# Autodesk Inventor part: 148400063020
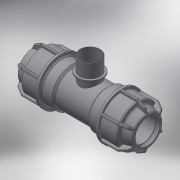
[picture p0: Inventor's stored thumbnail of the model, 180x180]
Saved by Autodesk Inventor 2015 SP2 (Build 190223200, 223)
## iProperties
Created: 2017-08
Part Number: 148400063020
Material: Generic
Description: PLASSON L.14 TEE MALE ADAPTOR (SILVER) 63-2"-63
Document SubType Name: Modeling
Designer: KIM
Density: 1 g/cm^3
Appearance: Default
Author: KIM
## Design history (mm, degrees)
derived "148400.ipt"
feature "Solid1::148400.ipt"
feature "Solid2::148400.ipt"
tag "TaggingFeature1"
body "Solid1"
body "Solid2"
other parameters: "d1" = 63, "d2" = 82, "d4" = 15 deg, "d5" = 54.12, "d6" = 17.8596, "d10" = 106, "d16" = 64.26, "d17" = 4.1, "d22" = 100.8, "d24" = 4.1, "d25" = 95.4, "d26" = 79.5, "d27" = 4.1, "d28" = 135 deg, "d29" = 2.46, "d31" = 3.15, "d46" = 150 deg, "d49" = 5.3, "d50" = 0, "d58" = 1.89, "d61" = 360 deg, "d63" = 56.7, "d64" = 119.5, "d80" = 90.72, "d81" = 5.04, "d84" = 4.1, "d94" = 84, "d96" = 59.614, "d108" = 1.89, "d111" = 0, "d113" = 56.7, "d114" = 71.5368, "d115" = 26, "d116" = 2.6, "d117" = 59.614, "d_" = 63, "R_" = 59.614, "E_" = 106, "H_" = 239, "l_" = 82, "l_2" = 26, "A_" = 84
